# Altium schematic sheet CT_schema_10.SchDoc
size 274 x 160 mm
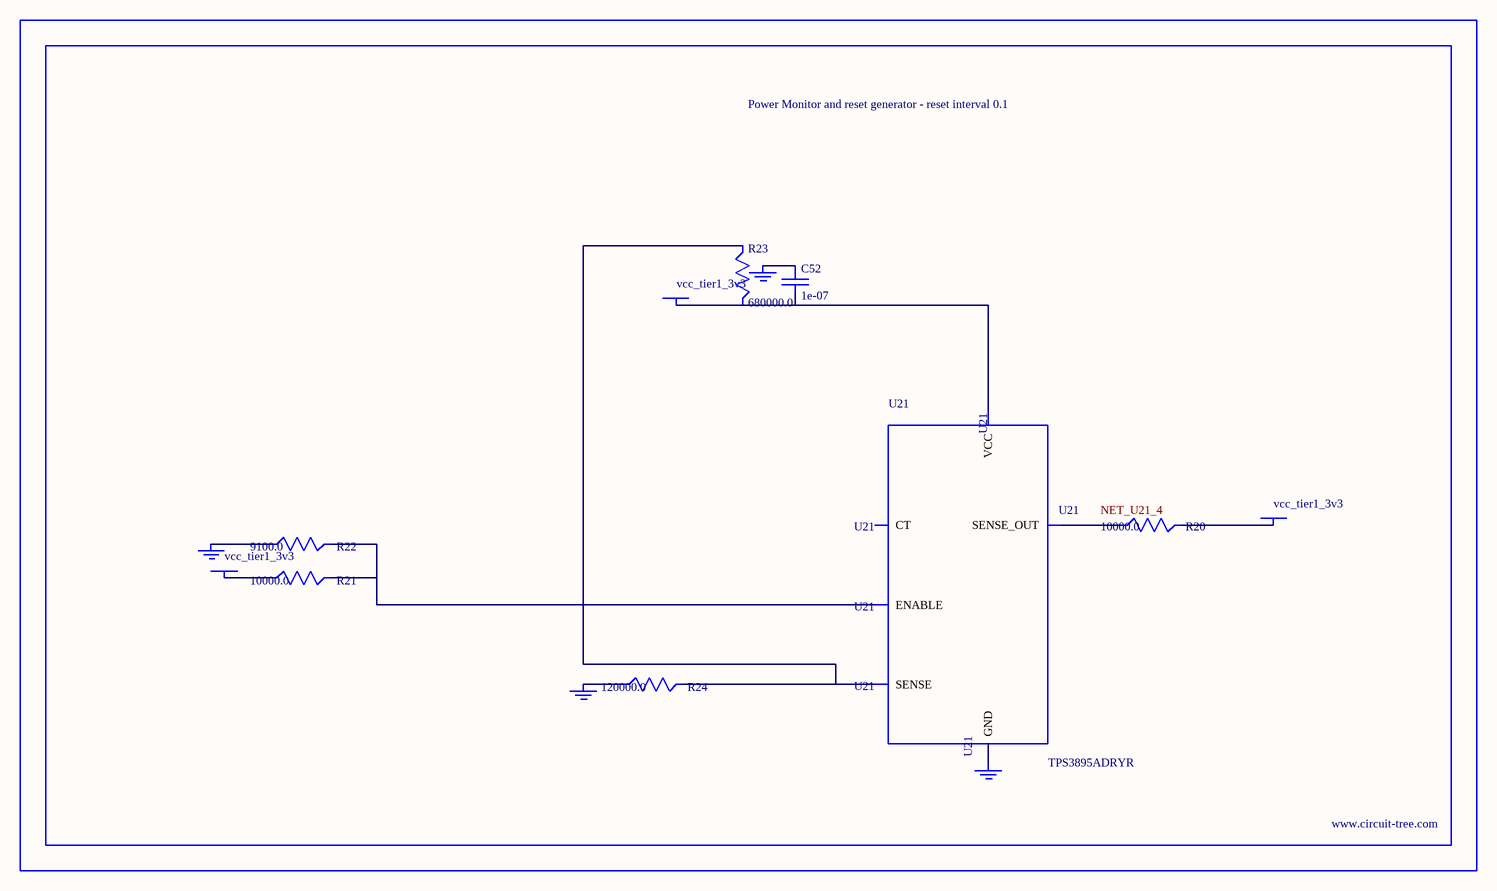
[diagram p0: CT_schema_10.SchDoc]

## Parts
BORDER9  (no value)
C52  1e-07  [C0402]
GND_INSTANCE_9_0  (no value)
GND_INSTANCE_9_1  (no value)
GND_INSTANCE_9_2  (no value)
GND_INSTANCE_9_3  (no value)
POWER_INSTANCE_9_0  vcc_tier1_3v3
POWER_INSTANCE_9_1  vcc_tier1_3v3
POWER_INSTANCE_9_2  vcc_tier1_3v3
R20  10000.0  [R0603]
R21  10000.0  [R0603]
R22  9100.0  [R0603]
R23  680000.0  [R0603]
R24  120000.0  [R0603]
U21  TPS3895ADRYR  [SON-6]

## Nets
NetC52_1: C52.1 GND_INSTANCE_9_2.0(GND)
NetC52_2: C52.2 POWER_INSTANCE_9_2.0(PWR) R23.2 U21.6(VCC)
NetGND_INSTANCE_9_0_0: GND_INSTANCE_9_0.0(GND) R22.1
NetGND_INSTANCE_9_1_0: GND_INSTANCE_9_1.0(GND) R24.1
NetGND_INSTANCE_9_3_0: GND_INSTANCE_9_3.0(GND) U21.2(GND)
NetPOWER_INSTANCE_9_0_0: POWER_INSTANCE_9_0.0(PWR) R21.1
NetPOWER_INSTANCE_9_1_0: POWER_INSTANCE_9_1.0(PWR) R20.2
NetR20_1: R20.1 U21.4(SENSE_OUT)
NetR21_2: R21.2 R22.2 U21.1(ENABLE)
NetR23_1: R23.1 R24.2 U21.3(SENSE)

Not connected (* = marked no-connect by the designer): U21 5(CT)

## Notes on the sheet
- Labels drawn without touching a wire or pin: NET_U21_4

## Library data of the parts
BORDER9 = BORDER_PAGE9
C52 = C0402C104K3RACTU
GND_INSTANCE_9_0-GND_INSTANCE_9_3 = GND
POWER_INSTANCE_9_0-POWER_INSTANCE_9_2 = PWR
R20 R21 = RC0603JR-0710KL
R22 = RC0603JR-079K1L
R23 = RC0603JR-07680KL
R24 = RC0603JR-07120KL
